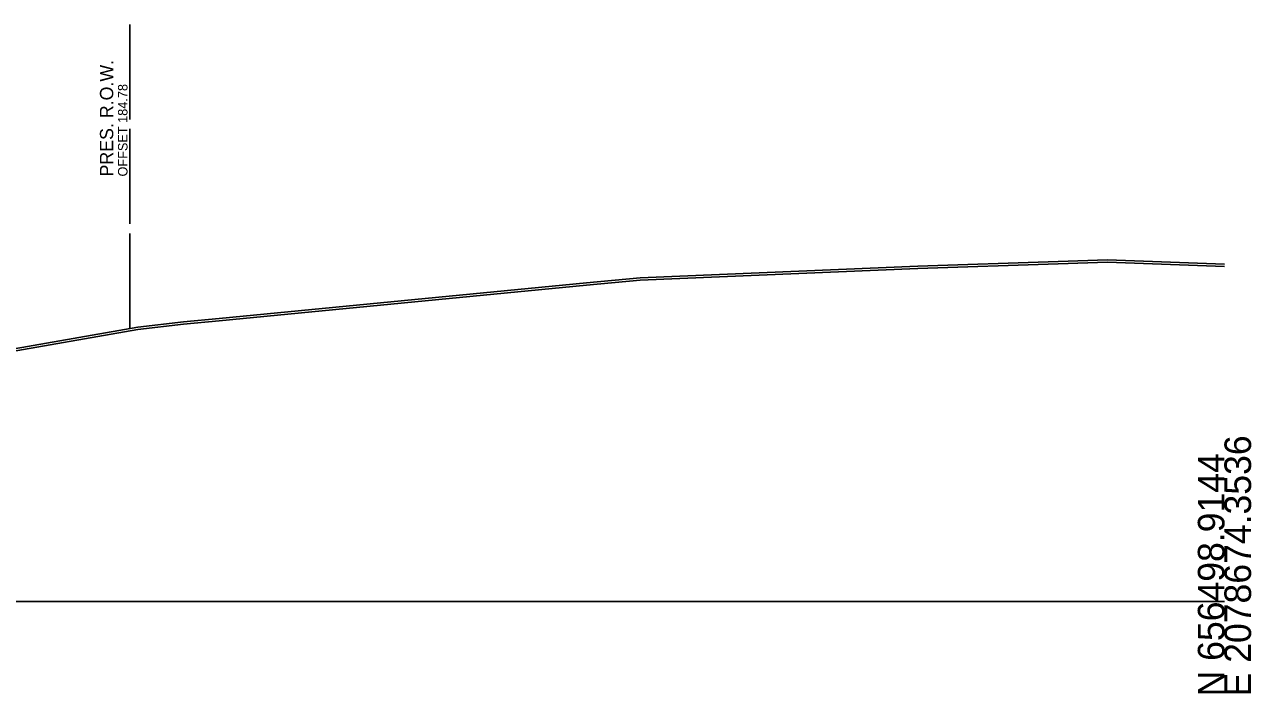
# Model space of a CAD drawing. Extents: x 5868 to 6683, y 2883 to 19120.
# Drawn here: x 6367.5 to 6496.6, y 14935.4 to 15005.8 of the extents above; entities that cross this region are included whole.
import ezdxf

# ---------------------------------------------------------------- set-up
doc = ezdxf.new("R2010")
doc.units = 0
for name, color, linetype in [('DESIGN - SHEET - Light Grid', 7, 'Continuous'), ('SURVEY - GROUND - Bottom of Topsoil Layer', 7, 'Continuous'), ('SURVEY - GROUND - Top of Ground', 7, 'Continuous'), ('SURVEY - PROPERTY - ROW Lines', 7, 'Continuous'), ('SURVEY - PROPERTY - ROW Lines Text', 7, 'Continuous')]:
    doc.layers.add(name, color=color, linetype=linetype)

msp = doc.modelspace()

# ---------------------------------------------------------------- linework, layer by layer
at = {"layer": 'DESIGN - SHEET - Light Grid'}
msp.add_line((6193.78, 14945.07), (6493.78, 14945.07), dxfattribs=at)
at = {"layer": 'SURVEY - GROUND - Bottom of Topsoil Layer'}
for p, q in [((6461.5, 14980.13), (6476.29, 14980.62)), ((6476.29, 14980.62), (6481.47, 14980.79)), ((6481.47, 14980.79), (6493.78, 14980.33)), ((6426.61, 14978.38), (6432.27, 14978.9)), ((6432.27, 14978.9), (6461.5, 14980.13)), ((6387.95, 14974.62), (6426.61, 14978.38)), ((6379.4, 14973.71), (6384.21, 14974.27)), ((6384.21, 14974.27), (6387.95, 14974.62)), ((6361.53, 14970.57), (6379.4, 14973.71))]:
    msp.add_line(p, q, dxfattribs=at)
at = {"layer": 'SURVEY - GROUND - Top of Ground'}
msp.add_lwpolyline([(6361.53, 14970.82), (6379.4, 14973.96), (6384.21, 14974.52), (6387.95, 14974.87), (6426.61, 14978.63), (6432.27, 14979.15), (6461.5, 14980.38), (6476.29, 14980.87), (6481.47, 14981.04), (6493.78, 14980.58)], dxfattribs=at)
at = {"layer": 'SURVEY - PROPERTY - ROW Lines'}
for p, q in [((6378.56, 14995.81), (6378.56, 15005.81)), ((6378.56, 14984.81), (6378.56, 14994.81)), ((6378.56, 14973.81), (6378.56, 14983.81))]:
    msp.add_line(p, q, dxfattribs=at)

# ---------------------------------------------------------------- texts
at = {"layer": 'DESIGN - SHEET - Light Grid'}
for s, p in [('E 2078674.3536', (6496.58, 14935.07)), ('N 656498.9144', (6493.78, 14935.07))]:
    msp.add_text(s, height=2.8, rotation=90, dxfattribs=at).set_placement(p)
at = {"layer": 'SURVEY - PROPERTY - ROW Lines Text'}
for s, height, p in [('PRES. R.O.W.', 1.4, (6376.81, 14989.81)), ('OFFSET 184.78', 1, (6378.31, 14989.81))]:
    msp.add_text(s, height=height, rotation=90, dxfattribs=at).set_placement(p)

doc.saveas('drawing.dxf')
